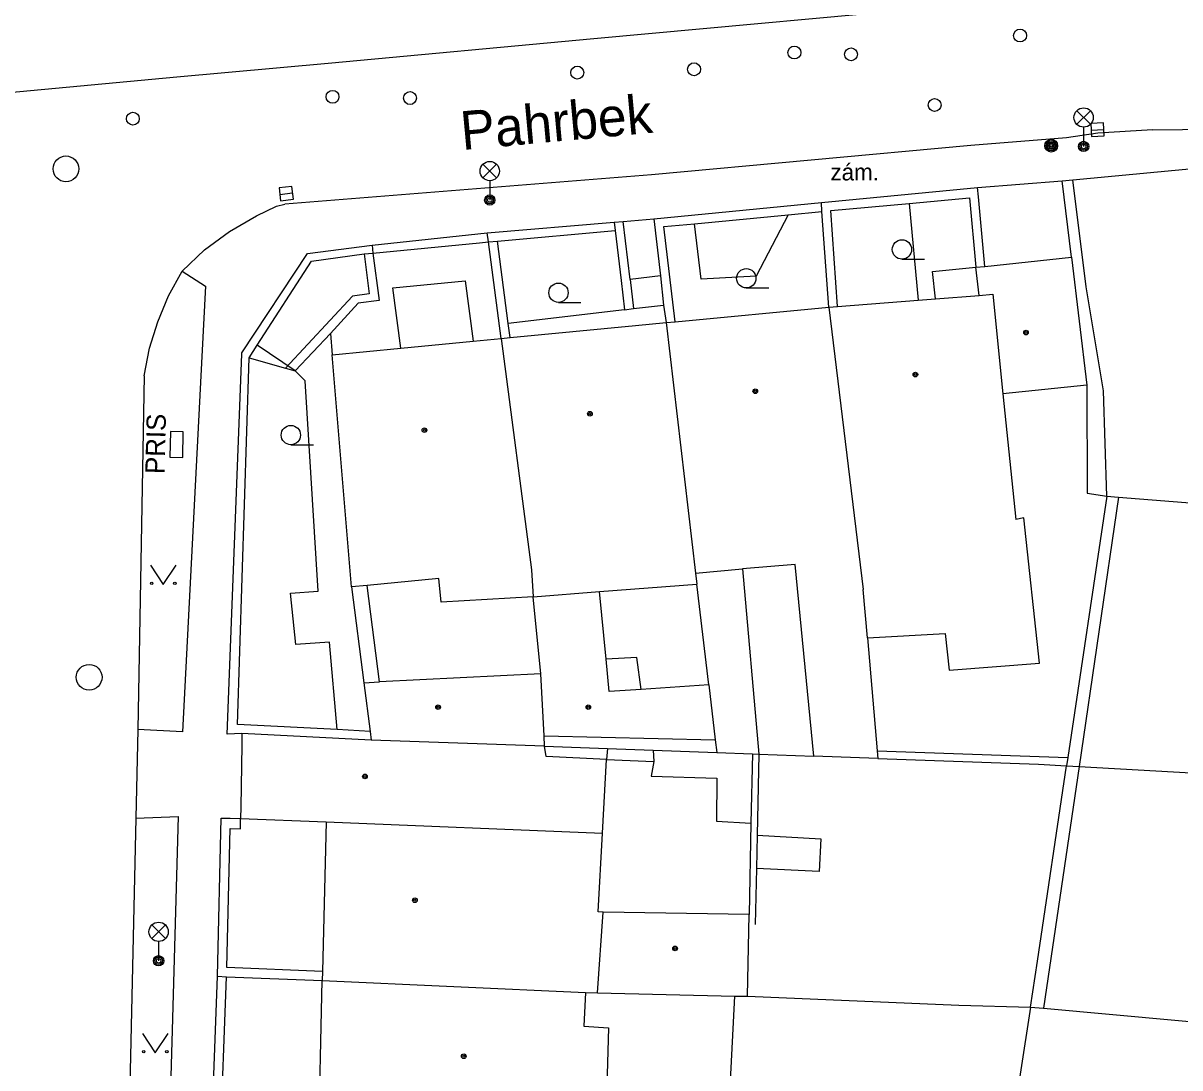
# Model space of a CAD drawing. Extents: x -596024 to -594475, y -1163820 to -1161957.
# Drawn here: x -595804.27 to -595759.31, y -1163020.04 to -1162979.46 of the extents above; entities that cross this region are included whole.
import ezdxf

# ---------------------------------------------------------------- set-up
doc = ezdxf.new("R2010")
doc.units = 0
for name, color, linetype in [('Level 10', 7, 'Continuous'), ('Level 11', 7, 'Continuous'), ('Level 24', 7, 'Continuous'), ('Level 25', 7, 'Continuous'), ('Level 27', 7, 'Continuous'), ('Level 28', 7, 'Continuous'), ('Level 33', 7, 'Continuous'), ('Level 36', 7, 'Continuous'), ('Level 39', 7, 'Continuous'), ('Level 40', 7, 'Continuous'), ('Level 41', 7, 'Continuous'), ('Level 49', 7, 'Continuous'), ('Level 5', 7, 'Continuous'), ('Level 6', 7, 'Continuous'), ('Level 7', 7, 'Continuous'), ('Level 8', 7, 'Continuous')]:
    doc.layers.add(name, color=color, linetype=linetype)

msp = doc.modelspace()

# ---------------------------------------------------------------- linework, layer by layer
at = {"layer": 'Level 10'}
for points in [[(-595886.79, -1162989.32), (-595875.89, -1162988.29), (-595874.88, -1162988.19), (-595865.06, -1162987.3), (-595846.54, -1162985.63), (-595834.03, -1162984.4), (-595833.92, -1162984.39), (-595827.57, -1162983.83), (-595811.92, -1162982.46), (-595810.38, -1162982.32), (-595807.74, -1162982.42), (-595798.29, -1162981.55), (-595792.41, -1162981.01), (-595782.08, -1162980.06), (-595767.36, -1162978.71), (-595765.31, -1162978.52), (-595764.65, -1162978.46), (-595760.16, -1162978.09)], [(-595760.38, -1162983.6), (-595762.5, -1162983.73), (-595763.71, -1162983.91), (-595767.43, -1162984.21), (-595779.85, -1162985.35), (-595794.09, -1162986.49)], [(-595760.38, -1162983.6), (-595756.86, -1162983.57), (-595752.76, -1162984.03)], [(-595798.09, -1162989.1), (-595797.22, -1162988.26), (-595796.25, -1162987.55), (-595795.2, -1162986.95), (-595794.42, -1162986.57), (-595794.09, -1162986.49)], [(-595799.56, -1162993.16), (-595799.35, -1162992.09), (-595799.03, -1162991.06), (-595798.61, -1162990.05), (-595798.09, -1162989.1)], [(-595799.56, -1162993.16), (-595799.81, -1163006.9)], [(-595799.81, -1163006.9), (-595799.88, -1163010.34)], [(-595799.88, -1163010.34), (-595800.17, -1163023.04)]]:
    msp.add_lwpolyline(points, dxfattribs=at)
at = {"layer": 'Level 11'}
for points in [[(-595763.52, -1162988.55), (-595763.88, -1162985.58)], [(-595762.15, -1162997.83), (-595762.28, -1162993.74), (-595762.95, -1162989.7), (-595763.47, -1162985.54)], [(-595769.83, -1162986.46), (-595769.48, -1162990.22)], [(-595774.53, -1162986.9), (-595775.78, -1162989.29), (-595777.92, -1162989.41), (-595778.18, -1162987.25)], [(-595781.3, -1162987.19), (-595781.26, -1162987.52)], [(-595780.68, -1162989.42), (-595780.95, -1162987.16)], [(-595781.26, -1162987.52), (-595781.03, -1162989.46), (-595780.9, -1162990.59), (-595780.55, -1162990.55)], [(-595790.7, -1162988.08), (-595790.67, -1162988.39)], [(-595791.01, -1162988.42), (-595790.82, -1162989.98), (-595791.47, -1162990.07), (-595794.07, -1162992.86)], [(-595790.67, -1162988.39), (-595790.43, -1162990.23), (-595791.24, -1162990.34), (-595792.32, -1162991.51)], [(-595798.09, -1162989.1), (-595797.18, -1162989.67), (-595797.32, -1162992.41)], [(-595768.81, -1162990.17), (-595768.93, -1162989.11), (-595767.24, -1162988.94)], [(-595779.5, -1162989.28), (-595780.68, -1162989.42)], [(-595780.68, -1162989.42), (-595780.55, -1162990.55)], [(-595780.55, -1162990.55), (-595779.38, -1162990.41)], [(-595780.9, -1162990.59), (-595785.41, -1162991.13)], [(-595794.07, -1162992.86), (-595793.69, -1162992.97), (-595792.32, -1162991.51)], [(-595792.32, -1162991.51), (-595792.25, -1162992.34)], [(-595789.59, -1162992.08), (-595786.77, -1162991.81)], [(-595793.69, -1162992.97), (-595795.17, -1162991.97)], [(-595797.32, -1162992.41), (-595798.07, -1163006.99), (-595799.81, -1163006.9)], [(-595795.48, -1162992.46), (-595794.07, -1162992.86)], [(-595792.06, -1163006.9), (-595792.36, -1163003.51), (-595793.67, -1163003.59), (-595793.87, -1163001.6), (-595792.8, -1163001.52), (-595793.31, -1162993.35), (-595793.69, -1162992.97)], [(-595762.92, -1162993.52), (-595762.91, -1162997.72), (-595762.15, -1162997.83)], [(-595762.15, -1162997.83), (-595763.66, -1163007.98)], [(-595761.69, -1162997.87), (-595763.23, -1163008.33)], [(-595762.15, -1162997.83), (-595761.69, -1162997.87)], [(-595761.69, -1162997.87), (-595748.63, -1162998.91)], [(-595776.31, -1163000.66), (-595775.67, -1163007.85)], [(-595791.5, -1163001.35), (-595791.02, -1163005.08)], [(-595790.42, -1163005.04), (-595790.9, -1163001.3)], [(-595777.62, -1163005.16), (-595778.08, -1163001.25)], [(-595780.25, -1163005.34), (-595780.41, -1163004.1), (-595781.61, -1163004.17)], [(-595795.76, -1163007.05), (-595796.34, -1163007.08)], [(-595784.02, -1163007.14), (-595777.37, -1163007.3)], [(-595781.56, -1163007.64), (-595781.59, -1163008.06)], [(-595781.59, -1163008.06), (-595779.76, -1163008.14)], [(-595779.78, -1163007.7), (-595779.76, -1163008.14)], [(-595777.31, -1163007.79), (-595775.92, -1163007.84)], [(-595775.92, -1163007.84), (-595775.99, -1163010.54)], [(-595775.92, -1163007.84), (-595775.67, -1163007.85)], [(-595775.67, -1163007.85), (-595775.74, -1163011)], [(-595775.67, -1163007.85), (-595773.53, -1163007.93)], [(-595771.08, -1163007.72), (-595763.66, -1163007.98)], [(-595771.05, -1163008.02), (-595764.8, -1163008.25), (-595763.71, -1163008.31)], [(-595763.66, -1163007.98), (-595763.71, -1163008.31)], [(-595779.76, -1163008.14), (-595779.86, -1163008.71), (-595777.3, -1163008.79), (-595777.32, -1163010.46), (-595775.99, -1163010.54)], [(-595765.11, -1163017.68), (-595764.84, -1163015.89), (-595763.71, -1163008.31)], [(-595763.23, -1163008.33), (-595764.61, -1163017.72)], [(-595763.71, -1163008.31), (-595763.23, -1163008.33)], [(-595763.23, -1163008.33), (-595748.33, -1163009.18)], [(-595799.88, -1163010.34), (-595798.24, -1163010.27), (-595798.47, -1163018.57)], [(-595775.99, -1163010.54), (-595776.05, -1163014.08)], [(-595775.74, -1163011), (-595773.26, -1163011.15), (-595773.33, -1163012.41), (-595775.76, -1163012.3)], [(-595775.74, -1163011), (-595775.76, -1163012.3)], [(-595775.76, -1163012.3), (-595775.81, -1163014.47)], [(-595776.93, -1163023.59), (-595776.6, -1163017.25)], [(-595776.11, -1163017.26), (-595767.9, -1163017.61), (-595765.11, -1163017.68)], [(-595765.11, -1163017.68), (-595765.52, -1163020.28), (-595765.7, -1163021.44), (-595766.12, -1163024.03)], [(-595765.11, -1163017.68), (-595764.61, -1163017.72)], [(-595764.61, -1163017.72), (-595756.81, -1163018.43), (-595748.6, -1163018.84)], [(-595798.47, -1163018.57), (-595798.6, -1163023.05), (-595800.17, -1163023.04)]]:
    msp.add_lwpolyline(points, dxfattribs=at)
at = {"layer": 'Level 24'}
msp.add_lwpolyline([(-595798.06, -1162996.335), (-595798.041, -1162995.335), (-595798.54, -1162995.325), (-595798.559, -1162996.325)], close=True, dxfattribs=at)
at = {"layer": 'Level 25'}
for radius in [0.25, 0.2, 0.15, 0.1, 0.05]:
    msp.add_circle((-595764.31, -1162984.22), radius, dxfattribs=at)
at = {"layer": 'Level 27'}
for p, q in [((-595762.76, -1162983.613), (-595762.26, -1162983.587)), ((-595794.288, -1162986.11), (-595793.792, -1162986.05))]:
    msp.add_line(p, q, dxfattribs=at)
for points in [[(-595762.747, -1162983.862), (-595762.248, -1162983.837), (-595762.273, -1162983.338), (-595762.772, -1162983.363)], [(-595794.259, -1162986.358), (-595793.762, -1162986.299), (-595793.821, -1162985.802), (-595794.318, -1162985.861)]]:
    msp.add_lwpolyline(points, close=True, dxfattribs=at)
for centre in [(-595802.6, -1162985.12), (-595801.7, -1163004.87)]:
    msp.add_circle(centre, 0.5, dxfattribs=at)
at = {"layer": 'Level 28'}
for centre in [(-595765.52, -1162979.94), (-595774.29, -1162980.6), (-595772.09, -1162980.67), (-595782.73, -1162981.38), (-595778.19, -1162981.25), (-595792.24, -1162982.32), (-595789.23, -1162982.37), (-595768.84, -1162982.64), (-595800, -1162983.17)]:
    msp.add_circle(centre, 0.25, dxfattribs=at)
at = {"layer": 'Level 33'}
for p, q in [((-595763.315, -1162983.39), (-595762.785, -1162982.86)), ((-595763.315, -1162982.86), (-595762.785, -1162983.39)), ((-595763.05, -1162983.5), (-595763.05, -1162984.25)), ((-595786.395, -1162985.47), (-595785.865, -1162984.94)), ((-595786.395, -1162984.94), (-595785.865, -1162985.47)), ((-595786.13, -1162985.58), (-595786.13, -1162986.33)), ((-595799.265, -1163015.02), (-595798.735, -1163014.49)), ((-595799.265, -1163014.49), (-595798.735, -1163015.02)), ((-595799, -1163015.13), (-595799, -1163015.88))]:
    msp.add_line(p, q, dxfattribs=at)
for centre, radius in [((-595763.05, -1162983.125), 0.375), ((-595763.05, -1162984.25), 0.2), ((-595763.05, -1162984.25), 0.145), ((-595763.05, -1162984.25), 0.0876), ((-595786.13, -1162985.205), 0.375), ((-595786.13, -1162986.33), 0.2), ((-595786.13, -1162986.33), 0.145), ((-595786.13, -1162986.33), 0.0876), ((-595799, -1163014.755), 0.375), ((-595799, -1163015.88), 0.2), ((-595799, -1163015.88), 0.145), ((-595799, -1163015.88), 0.0876)]:
    msp.add_circle(centre, radius, dxfattribs=at)
at = {"layer": 'Level 36'}
for p, q in [((-595770.11, -1162988.625), (-595769.235, -1162988.625)), ((-595776.16, -1162989.745), (-595775.285, -1162989.745)), ((-595783.46, -1162990.305), (-595782.585, -1162990.305)), ((-595793.86, -1162995.835), (-595792.985, -1162995.835))]:
    msp.add_line(p, q, dxfattribs=at)
for points in [[(-595799.32, -1163000.52), (-595798.82, -1163001.27), (-595798.32, -1163000.52)], [(-595799.63, -1163018.71), (-595799.13, -1163019.46), (-595798.63, -1163018.71)]]:
    msp.add_lwpolyline(points, dxfattribs=at)
for centre, radius in [((-595770.11, -1162988.25), 0.375), ((-595776.16, -1162989.37), 0.375), ((-595783.46, -1162989.93), 0.375), ((-595793.86, -1162995.46), 0.375), ((-595799.27, -1163001.22), 0.05), ((-595798.371, -1163001.22), 0.05), ((-595799.58, -1163019.41), 0.05), ((-595798.681, -1163019.41), 0.05)]:
    msp.add_circle(centre, radius, dxfattribs=at)
at = {"layer": 'Level 39'}
for centre, radius in [((-595765.29, -1162991.48), 0.09), ((-595765.29, -1162991.48), 0.0398), ((-595769.59, -1162993.11), 0.09), ((-595769.59, -1162993.11), 0.0398), ((-595775.81, -1162993.76), 0.09), ((-595775.81, -1162993.76), 0.0398), ((-595782.24, -1162994.63), 0.09), ((-595782.24, -1162994.63), 0.0398), ((-595788.67, -1162995.27), 0.09), ((-595788.67, -1162995.27), 0.0398), ((-595788.14, -1163006.03), 0.09), ((-595788.14, -1163006.03), 0.0398), ((-595782.3, -1163006.03), 0.09), ((-595782.3, -1163006.03), 0.0398), ((-595790.98, -1163008.72), 0.09), ((-595790.98, -1163008.72), 0.0398), ((-595789.04, -1163013.53), 0.09), ((-595789.04, -1163013.53), 0.0398), ((-595778.93, -1163015.4), 0.09), ((-595778.93, -1163015.4), 0.0398), ((-595787.14, -1163019.59), 0.09), ((-595787.14, -1163019.59), 0.0398)]:
    msp.add_circle(centre, radius, dxfattribs=at)
at = {"layer": 'Level 5'}
for points in [[(-595766.89, -1162988.91), (-595763.52, -1162988.55)], [(-595763.52, -1162988.55), (-595762.92, -1162993.52)], [(-595767.24, -1162988.94), (-595766.89, -1162988.91)], [(-595767.11, -1162990.04), (-595767.24, -1162988.94)], [(-595789.9, -1162989.74), (-595787.08, -1162989.47)], [(-595787.08, -1162989.47), (-595786.77, -1162991.81)], [(-595789.59, -1162992.08), (-595789.9, -1162989.74)], [(-595768.81, -1162990.17), (-595767.11, -1162990.04)], [(-595767.11, -1162990.04), (-595766.58, -1162989.99)], [(-595766.58, -1162989.99), (-595766.19, -1162993.86)], [(-595778.93, -1162991.06), (-595772.95, -1162990.49)], [(-595772.95, -1162990.49), (-595772.61, -1162990.46)], [(-595772.95, -1162990.49), (-595771.62, -1163001.46)], [(-595772.61, -1162990.46), (-595769.48, -1162990.22), (-595768.81, -1162990.17)], [(-595785.34, -1162991.67), (-595780.47, -1162991.2), (-595779.28, -1162991.09)], [(-595779.28, -1162991.09), (-595778.93, -1162991.06)], [(-595779.28, -1162991.09), (-595778.13, -1163000.82)], [(-595786.77, -1162991.81), (-595785.69, -1162991.71)], [(-595785.69, -1162991.71), (-595785.34, -1162991.67)], [(-595785.69, -1162991.71), (-595784.51, -1163000.7)], [(-595792.25, -1162992.34), (-595789.59, -1162992.08)], [(-595791.5, -1163001.35), (-595792.25, -1162992.34)], [(-595762.92, -1162993.52), (-595766.19, -1162993.86)], [(-595766.19, -1162993.86), (-595765.69, -1162998.74)], [(-595765.38, -1162998.68), (-595765.69, -1162998.74)], [(-595764.77, -1163004.32), (-595765.38, -1162998.68)], [(-595784.51, -1163000.7), (-595784.45, -1163001.74)], [(-595778.13, -1163000.82), (-595776.31, -1163000.66)], [(-595778.13, -1163000.82), (-595778.08, -1163001.25)], [(-595774.26, -1163000.49), (-595776.31, -1163000.66)], [(-595773.53, -1163007.93), (-595774.26, -1163000.49)], [(-595790.9, -1163001.3), (-595791.5, -1163001.35)], [(-595788.11, -1163001.03), (-595790.9, -1163001.3)], [(-595788.02, -1163001.95), (-595788.11, -1163001.03)], [(-595781.86, -1163001.54), (-595778.08, -1163001.25)], [(-595784.45, -1163001.74), (-595788.02, -1163001.95)], [(-595784.45, -1163001.74), (-595781.86, -1163001.54)], [(-595784.14, -1163004.74), (-595784.45, -1163001.74)], [(-595781.61, -1163004.17), (-595781.86, -1163001.54)], [(-595771.45, -1163003.33), (-595771.62, -1163001.46)], [(-595771.45, -1163003.33), (-595768.43, -1163003.17)], [(-595771.45, -1163003.33), (-595771.08, -1163007.72)], [(-595768.43, -1163003.17), (-595768.28, -1163004.59)], [(-595781.49, -1163005.42), (-595781.61, -1163004.17)], [(-595768.28, -1163004.59), (-595764.77, -1163004.32)], [(-595784.14, -1163004.74), (-595790.42, -1163005.04)], [(-595784.02, -1163007.14), (-595784.14, -1163004.74)], [(-595791.02, -1163005.08), (-595790.42, -1163005.04)], [(-595791.02, -1163005.08), (-595790.78, -1163006.97)], [(-595780.25, -1163005.34), (-595781.49, -1163005.42)], [(-595777.62, -1163005.16), (-595780.25, -1163005.34)], [(-595777.62, -1163005.16), (-595777.37, -1163007.3)], [(-595795.76, -1163007.05), (-595795.77, -1163007.5)], [(-595790.74, -1163007.31), (-595795.76, -1163007.05)], [(-595790.78, -1163006.97), (-595790.74, -1163007.31)], [(-595784, -1163007.55), (-595784.02, -1163007.14)], [(-595795.77, -1163007.5), (-595795.81, -1163009.9)], [(-595784, -1163007.55), (-595790.74, -1163007.31)], [(-595783.94, -1163007.95), (-595784, -1163007.55)], [(-595784, -1163007.55), (-595781.56, -1163007.64)], [(-595781.56, -1163007.64), (-595779.78, -1163007.7)], [(-595777.37, -1163007.3), (-595777.31, -1163007.79)], [(-595781.59, -1163008.06), (-595783.94, -1163007.95)], [(-595781.75, -1163010.93), (-595781.59, -1163008.06)], [(-595779.78, -1163007.7), (-595777.31, -1163007.79)], [(-595771.05, -1163008.02), (-595773.53, -1163007.93)], [(-595771.08, -1163007.72), (-595771.05, -1163008.02)], [(-595795.81, -1163009.9), (-595795.82, -1163010.35)], [(-595795.82, -1163010.35), (-595792.49, -1163010.49)], [(-595792.49, -1163010.49), (-595792.63, -1163016.3)], [(-595792.49, -1163010.49), (-595781.75, -1163010.93)], [(-595781.92, -1163013.98), (-595781.75, -1163010.93)], [(-595781.94, -1163017.13), (-595781.72, -1163013.99)], [(-595781.72, -1163013.99), (-595781.92, -1163013.98)], [(-595776.05, -1163014.08), (-595781.72, -1163013.99)], [(-595776.11, -1163017.26), (-595776.05, -1163014.08)], [(-595792.79, -1163023.17), (-595792.64, -1163016.65)], [(-595792.63, -1163016.3), (-595792.64, -1163016.65)], [(-595792.64, -1163016.65), (-595782.41, -1163017.11)], [(-595782.41, -1163017.11), (-595782.48, -1163018.42)], [(-595782.41, -1163017.11), (-595781.94, -1163017.13)], [(-595781.94, -1163017.13), (-595776.6, -1163017.25), (-595776.11, -1163017.26)], [(-595782.48, -1163018.42), (-595781.52, -1163018.49)], [(-595781.52, -1163018.49), (-595781.58, -1163020.75)]]:
    msp.add_lwpolyline(points, dxfattribs=at)
at = {"layer": 'Level 6'}
msp.add_lwpolyline([(-595795.77, -1163007.5), (-595795.81, -1163009.9)], dxfattribs=at)
at = {"layer": 'Level 7'}
for points in [[(-595763.47, -1162985.54), (-595753.18, -1162984.57), (-595748.92, -1162988.33), (-595748.67, -1162990.99)], [(-595763.88, -1162985.58), (-595763.47, -1162985.54)], [(-595773.24, -1162986.42), (-595767.18, -1162985.85)], [(-595766.89, -1162988.91), (-595767.14, -1162986.2), (-595767.18, -1162985.85)], [(-595779.75, -1162987.06), (-595773.24, -1162986.42)], [(-595773.22, -1162986.77), (-595773.24, -1162986.42)], [(-595772.87, -1162986.74), (-595769.83, -1162986.46), (-595767.49, -1162986.24)], [(-595767.49, -1162986.24), (-595767.24, -1162988.94)], [(-595779.36, -1162987.36), (-595778.18, -1162987.25), (-595774.53, -1162986.9), (-595773.22, -1162986.77)], [(-595772.95, -1162990.49), (-595773.22, -1162986.77)], [(-595772.61, -1162990.46), (-595772.87, -1162986.74)], [(-595786.23, -1162987.6), (-595781.3, -1162987.19)], [(-595781.3, -1162987.19), (-595780.95, -1162987.16)], [(-595780.95, -1162987.16), (-595779.75, -1162987.06)], [(-595779.75, -1162987.06), (-595779.5, -1162989.28)], [(-595778.93, -1162991.06), (-595779.36, -1162987.36)], [(-595790.7, -1162988.08), (-595786.23, -1162987.6)], [(-595786.18, -1162987.96), (-595786.23, -1162987.6)], [(-595785.83, -1162987.93), (-595781.26, -1162987.52)], [(-595793.21, -1162988.41), (-595790.7, -1162988.08)], [(-595790.67, -1162988.39), (-595786.53, -1162987.99), (-595786.18, -1162987.96)], [(-595786.18, -1162987.96), (-595785.83, -1162987.93)], [(-595785.69, -1162991.71), (-595786.18, -1162987.96)], [(-595785.34, -1162991.67), (-595785.41, -1162991.13), (-595785.83, -1162987.93)], [(-595796.34, -1163007.08), (-595795.77, -1162992.32), (-595795.77, -1162992.26), (-595793.21, -1162988.41)], [(-595795.48, -1162992.46), (-595795.17, -1162991.97), (-595793.06, -1162988.71)], [(-595793.06, -1162988.71), (-595791.01, -1162988.42)], [(-595791.01, -1162988.42), (-595790.67, -1162988.39)], [(-595779.5, -1162989.28), (-595779.38, -1162990.41)], [(-595779.38, -1162990.41), (-595779.28, -1162991.09)], [(-595790.78, -1163006.97), (-595792.06, -1163006.9), (-595795.94, -1163006.7), (-595795.48, -1162992.46)], [(-595796.71, -1163016.48), (-595796.57, -1163010.34)], [(-595796.57, -1163010.34), (-595796.22, -1163010.34)], [(-595792.63, -1163016.3), (-595796.35, -1163016.14), (-595796.22, -1163010.74), (-595795.82, -1163010.75), (-595795.82, -1163010.35)], [(-595796.22, -1163010.34), (-595795.82, -1163010.35)], [(-595796.96, -1163023.1), (-595796.79, -1163018.58), (-595796.71, -1163016.48)], [(-595796.71, -1163016.48), (-595796.36, -1163016.5)], [(-595796.61, -1163023.11), (-595796.36, -1163016.5)], [(-595796.36, -1163016.5), (-595792.64, -1163016.65)]]:
    msp.add_lwpolyline(points, dxfattribs=at)
at = {"layer": 'Level 8'}
msp.add_lwpolyline([(-595767.18, -1162985.85), (-595763.88, -1162985.58)], dxfattribs=at)

# ---------------------------------------------------------------- texts
at = {"layer": 'Level 40'}
msp.add_text('zám.', height=0.65, dxfattribs=at).set_placement((-595772.89, -1162985.57))
at = {"layer": 'Level 41'}
msp.add_text('PRIS', height=0.75, rotation=88.59, dxfattribs=at).set_placement((-595798.77, -1162996.98))
at = {"layer": 'Level 49'}
msp.add_text('Pahrbek', height=1.5, rotation=5.2, dxfattribs=at).set_placement((-595787.2, -1162984.39))

doc.saveas('drawing.dxf')
